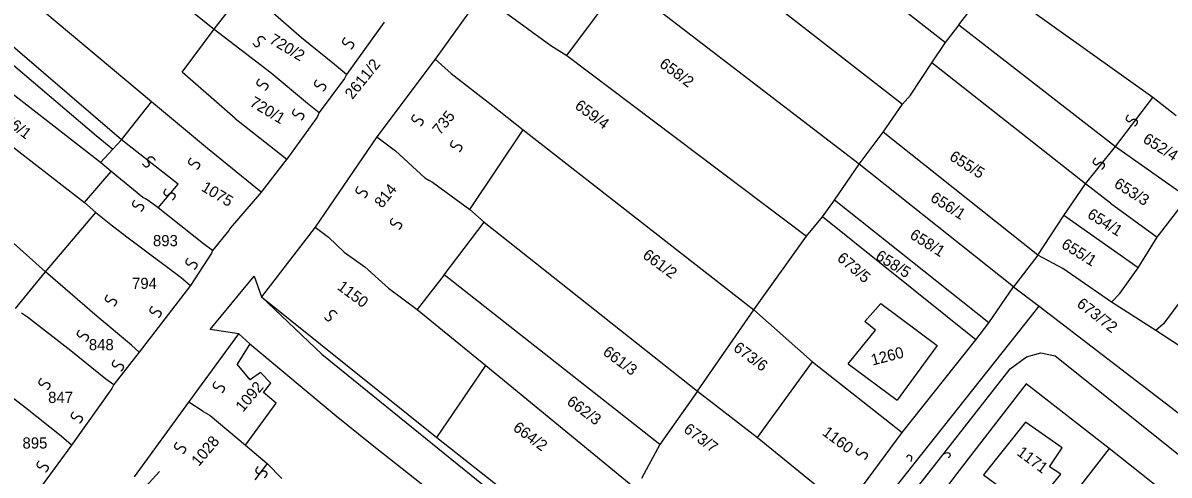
# Model space of a CAD drawing. Extents: x -581999 to -572728, y -1219553 to -1212032.
# Drawn here: x -577734.8 to -577529.2, y -1214895.3 to -1214814.1 of the extents above; entities that cross this region are included whole.
import ezdxf

# ---------------------------------------------------------------- set-up
doc = ezdxf.new("R2010")
doc.units = 0
for name, color, linetype in [('Vrstva 1', 7, 'Continuous'), ('Vrstva 2', 7, 'Continuous'), ('Vrstva 4', 7, 'Continuous'), ('Vrstva 6', 7, 'Continuous')]:
    doc.layers.add(name, color=color, linetype=linetype)

msp = doc.modelspace()

# ---------------------------------------------------------------- linework, layer by layer
at = {"layer": 'Vrstva 1'}
for p, q in [((-577548.056, -1214848.672), (-577544.197, -1214842.995)), ((-577552.774, -1214855.823), (-577548.056, -1214848.672)), ((-577534.754, -1214858.098), (-577548.056, -1214848.672)), ((-577700.798, -1214855), (-577700.97, -1214855.459)), ((-577700.97, -1214855.459), (-577704.745, -1214861.238)), ((-577701.189, -1214869.169), (-577693.334, -1214859.561)), ((-577693.334, -1214859.561), (-577691.998, -1214863.305)), ((-577704.745, -1214861.238), (-577713.952, -1214873.202)), ((-577681.203, -1214873.576), (-577691.998, -1214863.305)), ((-577602.086, -1214927.442), (-577552.514, -1214864.961)), ((-577696.075, -1214869.89), (-577701.189, -1214869.169)), ((-577554.783, -1214874.062), (-577552.226, -1214873.353)), ((-577552.226, -1214873.353), (-577549.644, -1214873.861)), ((-577681.203, -1214873.576), (-577612.266, -1214929.311)), ((-577557.705, -1214876.188), (-577554.783, -1214874.062)), ((-577549.644, -1214873.861), (-577480.978, -1214928.785)), ((-577599.697, -1214929.758), (-577557.705, -1214876.188)), ((-577702.462, -1214883.865), (-577705.058, -1214882.189))]:
    msp.add_line(p, q, dxfattribs=at)
for points in [[(-577747.607, -1214777.644), (-577700.52, -1214815.294)], [(-577717.101, -1214835.147), (-577773.13, -1214787)], [(-577711.749, -1214828.273), (-577757.801, -1214789.75)], [(-577602.684, -1214791.504), (-577569.32, -1214817.641)], [(-577770.074, -1214801.603), (-577765.899, -1214796.69), (-577721.694, -1214834.344), (-577718.663, -1214836.797)], [(-577610.911, -1214802.293), (-577577.009, -1214828.694)], [(-577637.213, -1214820.018), (-577627.323, -1214806.643)], [(-577566.929, -1214814.48), (-577561.078, -1214806.816)], [(-577527.934, -1214830.82), (-577532.103, -1214827.51), (-577561.078, -1214806.816)], [(-577700.52, -1214815.294), (-577695.029, -1214808.235)], [(-577652.443, -1214808.875), (-577660.874, -1214820.637)], [(-577584.785, -1214839.458), (-577624.766, -1214808.82)], [(-577684.856, -1214816.822), (-577690.887, -1214811.561)], [(-577649.144, -1214811.619), (-577640.086, -1214818.2)], [(-577696.723, -1214831.286), (-577706.264, -1214822.979), (-577700.52, -1214815.294)], [(-577700.52, -1214815.294), (-577690.3, -1214823.096)], [(-577669.983, -1214814.006), (-577676.755, -1214823.38)], [(-577569.32, -1214817.641), (-577567.041, -1214814.704), (-577566.929, -1214814.48)], [(-577566.929, -1214814.48), (-577538.793, -1214836.285), (-577525.86, -1214845.454)], [(-577678.915, -1214821.626), (-577684.856, -1214816.822)], [(-577571.772, -1214821.326), (-577569.32, -1214817.641)], [(-577640.086, -1214818.2), (-577637.213, -1214820.018)], [(-577637.213, -1214820.018), (-577594.254, -1214852.405)], [(-577720.879, -1214839.207), (-577744.685, -1214820.71)], [(-577676.755, -1214823.38), (-577678.915, -1214821.626)], [(-577660.874, -1214820.637), (-577671.346, -1214834.593)], [(-577660.874, -1214820.637), (-577657.985, -1214823.242)], [(-577575.563, -1214827.133), (-577571.772, -1214821.326)], [(-577539.717, -1214846.496), (-577544.197, -1214842.995), (-577571.772, -1214821.326)], [(-577690.3, -1214823.096), (-577683.729, -1214828.543)], [(-577676.755, -1214823.38), (-577677.13, -1214824.143), (-577681.659, -1214830.206)], [(-577657.985, -1214823.242), (-577650.807, -1214828.796)], [(-577749.226, -1214826.599), (-577723.731, -1214846.371)], [(-577717.101, -1214835.147), (-577711.749, -1214828.273)], [(-577701.666, -1214836.676), (-577711.749, -1214828.273)], [(-577577.009, -1214828.694), (-577575.563, -1214827.133)], [(-577730.767, -1214858.778), (-577764.668, -1214828.469), (-577768.339, -1214829.671)], [(-577681.659, -1214830.206), (-577682.033, -1214831.059), (-577687.459, -1214838.567)], [(-577683.729, -1214828.543), (-577681.659, -1214830.206)], [(-577650.807, -1214828.796), (-577645.065, -1214833.33)], [(-577580.464, -1214833.719), (-577577.009, -1214828.694)], [(-577696.723, -1214831.286), (-577689.708, -1214836.775)], [(-577654.62, -1214847.611), (-577645.065, -1214833.33)], [(-577645.065, -1214833.33), (-577603.67, -1214865.62)], [(-577584.785, -1214839.458), (-577580.464, -1214833.719)], [(-577552.774, -1214855.823), (-577580.464, -1214833.719)], [(-577718.663, -1214836.797), (-577717.101, -1214835.147)], [(-577671.346, -1214834.593), (-577682.381, -1214850.79)], [(-577671.346, -1214834.593), (-577667.983, -1214837.072)], [(-577720.879, -1214839.207), (-577718.663, -1214836.797)], [(-577692.088, -1214844.479), (-577701.666, -1214836.676)], [(-577687.459, -1214838.567), (-577687.844, -1214838.976), (-577692.088, -1214844.479)], [(-577689.708, -1214836.775), (-577687.459, -1214838.567)], [(-577667.983, -1214837.072), (-577662.684, -1214841.939), (-577662.021, -1214842.337)], [(-577530.475, -1214851.501), (-577525.86, -1214845.454), (-577519.424, -1214837.028)], [(-577718.988, -1214840.776), (-577720.879, -1214839.207)], [(-577589.243, -1214845.934), (-577584.785, -1214839.458)], [(-577557.084, -1214861.5), (-577584.785, -1214839.458)], [(-577723.731, -1214846.371), (-577718.988, -1214840.776)], [(-577713.282, -1214845.445), (-577718.988, -1214840.776)], [(-577662.021, -1214842.337), (-577661.358, -1214842.735), (-577654.62, -1214847.611)], [(-577692.088, -1214844.479), (-577692.361, -1214844.843), (-577697.621, -1214850.934)], [(-577723.731, -1214846.371), (-577721.75, -1214848.124)], [(-577712.365, -1214846.024), (-577712.907, -1214845.638), (-577713.282, -1214845.445)], [(-577710.522, -1214847.336), (-577712.365, -1214846.024)], [(-577591.38, -1214848.924), (-577589.243, -1214845.934)], [(-577561.54, -1214867.975), (-577589.243, -1214845.934)], [(-577539.717, -1214846.496), (-577531.358, -1214852.586)], [(-577730.767, -1214858.778), (-577721.75, -1214848.124)], [(-577721.75, -1214848.124), (-577718.76, -1214850.552)], [(-577702.419, -1214853.799), (-577710.522, -1214847.336)], [(-577654.62, -1214847.611), (-577652.082, -1214849.875)], [(-577718.76, -1214850.552), (-577715.945, -1214852.669)], [(-577697.621, -1214850.934), (-577697.884, -1214851.366), (-577700.798, -1214855)], [(-577682.381, -1214850.79), (-577691.998, -1214863.305), (-577660.574, -1214888.531)], [(-577682.381, -1214850.79), (-577679.964, -1214852.554)], [(-577659.241, -1214859.335), (-577652.082, -1214849.875)], [(-577652.082, -1214849.875), (-577613.823, -1214880.19)], [(-577594.254, -1214852.405), (-577591.38, -1214848.924)], [(-577563.878, -1214870.987), (-577591.38, -1214848.924)], [(-577715.945, -1214852.669), (-577706.416, -1214859.808)], [(-577679.964, -1214852.554), (-577677.205, -1214855.268)], [(-577603.67, -1214865.62), (-577594.254, -1214852.405)], [(-577538.052, -1214862.662), (-577534.754, -1214858.098), (-577531.358, -1214852.586), (-577530.475, -1214851.501)], [(-577700.798, -1214855), (-577702.419, -1214853.799)], [(-577677.205, -1214855.268), (-577673.448, -1214857.878)], [(-577552.774, -1214855.823), (-577557.084, -1214861.5)], [(-577548.247, -1214858.213), (-577552.774, -1214855.823)], [(-577736.161, -1214865.367), (-577730.767, -1214858.778)], [(-577721.494, -1214866.804), (-577730.767, -1214858.778)], [(-577673.448, -1214857.878), (-577669.253, -1214861.724)], [(-577539.534, -1214864.221), (-577548.247, -1214858.213)], [(-577522.093, -1214857.171), (-577530.222, -1214868.102)], [(-577706.416, -1214859.808), (-577704.745, -1214861.238)], [(-577659.241, -1214859.335), (-577664.062, -1214865.579)], [(-577620.542, -1214889.762), (-577659.241, -1214859.335)], [(-577669.253, -1214861.724), (-577664.062, -1214865.579)], [(-577561.54, -1214867.975), (-577557.084, -1214861.5)], [(-577557.084, -1214861.5), (-577552.514, -1214864.961), (-577474.403, -1214924.888)], [(-577539.534, -1214864.221), (-577538.052, -1214862.662)], [(-577586.797, -1214875.311), (-577581.884, -1214869.252), (-577583.756, -1214867.716), (-577580.923, -1214864.498), (-577570.808, -1214871.999), (-577577.994, -1214881.849)], [(-577531.591, -1214869.326), (-577539.534, -1214864.221)], [(-577735.06, -1214866.132), (-577733.959, -1214866.896), (-577726.213, -1214872.899)], [(-577715.338, -1214871.968), (-577721.494, -1214866.804)], [(-577664.062, -1214865.579), (-577651.765, -1214875.618)], [(-577613.823, -1214880.19), (-577603.67, -1214865.62)], [(-577603.67, -1214865.62), (-577593.157, -1214874.941)], [(-577563.878, -1214870.987), (-577561.54, -1214867.975)], [(-577530.222, -1214868.102), (-577531.591, -1214869.326)], [(-577523.65, -1214874.542), (-577531.591, -1214869.326)], [(-577714.791, -1214895.569), (-577705.058, -1214882.189), (-577696.075, -1214869.89), (-577694.087, -1214871.7)], [(-577577.097, -1214887.628), (-577563.878, -1214870.987)], [(-577726.213, -1214872.899), (-577719.91, -1214877.975)], [(-577713.952, -1214873.202), (-577718.469, -1214878.991)], [(-577713.952, -1214873.202), (-577715.338, -1214871.968)], [(-577694.087, -1214871.7), (-577696.356, -1214875.348)], [(-577694.087, -1214871.7), (-577678.626, -1214884.607)], [(-577694.881, -1214889.88), (-577689.381, -1214882.379), (-577691.631, -1214880.457), (-577690.308, -1214878.752), (-577692.182, -1214876.833), (-577694.068, -1214878.154), (-577696.356, -1214875.348)], [(-577603.044, -1214888.541), (-577593.157, -1214874.941)], [(-577593.157, -1214874.941), (-577577.097, -1214887.628)], [(-577586.797, -1214875.311), (-577577.994, -1214881.849)], [(-577660.574, -1214888.531), (-577651.765, -1214875.618)], [(-577651.765, -1214875.618), (-577625.058, -1214897.575)], [(-577718.469, -1214878.991), (-577718.834, -1214879.716), (-577726.097, -1214889.907)], [(-577719.91, -1214877.975), (-577718.469, -1214878.991)], [(-577554.825, -1214878.905), (-577567.255, -1214894.961), (-577573.728, -1214903.608), (-577575.654, -1214907.252)], [(-577539.921, -1214890.466), (-577554.825, -1214878.905)], [(-577734.33, -1214883.219), (-577736.764, -1214881.349)], [(-577613.823, -1214880.19), (-577620.542, -1214889.762)], [(-577613.823, -1214880.19), (-577603.044, -1214888.541)], [(-577727.937, -1214888.295), (-577734.33, -1214883.219)], [(-577702.462, -1214883.865), (-577701.244, -1214884.58), (-577694.881, -1214889.88)], [(-577678.626, -1214884.607), (-577672.441, -1214889.588)], [(-577554.953, -1214885.746), (-577562.512, -1214895.211), (-577553.899, -1214901.554), (-577548.608, -1214895.12), (-577550.668, -1214893.772), (-577548.398, -1214890.362), (-577554.953, -1214885.746)], [(-577587.23, -1214901.351), (-577577.097, -1214887.628)], [(-577726.097, -1214889.907), (-577737.394, -1214905.307)], [(-577726.097, -1214889.907), (-577727.937, -1214888.295)], [(-577694.881, -1214889.88), (-577691.016, -1214893.162)], [(-577672.441, -1214889.588), (-577638.078, -1214916.756), (-577639.86, -1214918.987)], [(-577660.574, -1214888.531), (-577633.597, -1214909.776)], [(-577620.542, -1214889.762), (-577623.865, -1214895.874)], [(-577603.044, -1214888.541), (-577587.23, -1214901.351)], [(-577539.921, -1214890.466), (-577553.545, -1214908.032)], [(-577524.564, -1214902.68), (-577539.921, -1214890.466)], [(-577691.016, -1214893.162), (-577688.368, -1214895.874)]]:
    msp.add_lwpolyline(points, dxfattribs=at)
at = {"layer": 'Vrstva 4'}
for p, q in [((-577538.793, -1214836.285), (-577532.103, -1214827.51)), ((-577544.197, -1214842.995), (-577538.793, -1214836.285))]:
    msp.add_line(p, q, dxfattribs=at)
for points in [[(-577706.984, -1214843.089), (-577717.101, -1214835.147)], [(-577710.522, -1214847.336), (-577706.984, -1214843.089)], [(-577691.016, -1214893.162), (-577693.207, -1214896.103)], [(-577710.313, -1214894.612), (-577712.842, -1214897.34)]]:
    msp.add_lwpolyline(points, dxfattribs=at)
at = {"layer": 'Vrstva 6'}
for points, degree in [([(-577693.561, -1214817.824), (-577693.081, -1214818.531), (-577692.387, -1214818.22), (-577692.31, -1214817.82), (-577692.546, -1214817.475), (-577692.631, -1214817.143), (-577692.549, -1214816.853), (-577692.405, -1214816.673), (-577692.169, -1214816.545), (-577691.804, -1214816.581), (-577691.377, -1214817.02), (-577691.322, -1214817.193)], 2), ([(-577677.061, -1214816.788), (-577677.648, -1214817.41), (-577677.193, -1214818.019), (-577676.787, -1214818.007), (-577676.501, -1214817.702), (-577676.195, -1214817.548), (-577675.895, -1214817.564), (-577675.688, -1214817.666), (-577675.512, -1214817.869), (-577675.467, -1214818.233), (-577675.802, -1214818.745), (-577675.96, -1214818.837)], 2), ([(-577692.45, -1214824.191), (-577693.037, -1214824.813), (-577692.582, -1214825.422), (-577692.176, -1214825.41), (-577691.89, -1214825.105), (-577691.584, -1214824.951), (-577691.284, -1214824.967), (-577691.077, -1214825.069), (-577690.901, -1214825.272), (-577690.856, -1214825.636), (-577691.191, -1214826.148), (-577691.349, -1214826.24)], 2), ([(-577682.086, -1214824.348), (-577682.673, -1214824.97), (-577682.218, -1214825.579), (-577681.812, -1214825.567), (-577681.526, -1214825.262), (-577681.22, -1214825.108), (-577680.92, -1214825.124), (-577680.713, -1214825.226), (-577680.537, -1214825.429), (-577680.492, -1214825.793), (-577680.827, -1214826.305), (-577680.985, -1214826.397)], 2), ([(-577686.012, -1214829.546), (-577686.599, -1214830.168), (-577686.144, -1214830.777), (-577685.738, -1214830.765), (-577685.452, -1214830.46), (-577685.146, -1214830.306), (-577684.846, -1214830.322), (-577684.639, -1214830.424), (-577684.463, -1214830.627), (-577684.418, -1214830.991), (-577684.753, -1214831.503), (-577684.911, -1214831.595)], 2), ([(-577664.615, -1214830.596), (-577665.202, -1214831.218), (-577664.747, -1214831.827), (-577664.341, -1214831.815), (-577664.055, -1214831.51), (-577663.749, -1214831.356), (-577663.449, -1214831.372), (-577663.242, -1214831.474), (-577663.066, -1214831.677), (-577663.021, -1214832.041), (-577663.356, -1214832.553), (-577663.514, -1214832.645)], 2), ([(-577536.477, -1214830.622), (-577537.064, -1214831.244), (-577536.609, -1214831.853), (-577536.203, -1214831.841), (-577535.917, -1214831.536), (-577535.611, -1214831.382), (-577535.311, -1214831.398), (-577535.104, -1214831.5), (-577534.928, -1214831.703), (-577534.883, -1214832.067), (-577535.218, -1214832.579), (-577535.376, -1214832.671)], 2), ([(-577657.668, -1214835.238), (-577658.255, -1214835.86), (-577657.8, -1214836.469), (-577657.394, -1214836.457), (-577657.108, -1214836.152), (-577656.802, -1214835.998), (-577656.502, -1214836.014), (-577656.295, -1214836.116), (-577656.119, -1214836.319), (-577656.074, -1214836.683), (-577656.409, -1214837.195), (-577656.567, -1214837.287)], 2), ([(-577713.347, -1214839.402), (-577712.867, -1214840.109), (-577712.173, -1214839.798), (-577712.096, -1214839.398), (-577712.332, -1214839.053), (-577712.417, -1214838.721), (-577712.335, -1214838.431), (-577712.191, -1214838.251), (-577711.955, -1214838.123), (-577711.59, -1214838.159), (-577711.163, -1214838.598), (-577711.108, -1214838.771)], 2), ([(-577704.699, -1214838.366), (-577705.286, -1214838.988), (-577704.831, -1214839.597), (-577704.425, -1214839.585), (-577704.139, -1214839.28), (-577703.833, -1214839.126), (-577703.533, -1214839.142), (-577703.326, -1214839.244), (-577703.15, -1214839.447), (-577703.105, -1214839.811), (-577703.44, -1214840.323), (-577703.598, -1214840.415)], 2), ([(-577542.395, -1214838.365), (-577542.982, -1214838.987), (-577542.527, -1214839.596), (-577542.121, -1214839.584), (-577541.835, -1214839.279), (-577541.529, -1214839.125), (-577541.229, -1214839.141), (-577541.022, -1214839.243), (-577540.846, -1214839.446), (-577540.801, -1214839.81), (-577541.136, -1214840.322), (-577541.294, -1214840.414)], 2), ([(-577709.096, -1214843.878), (-577709.683, -1214844.5), (-577709.228, -1214845.109), (-577708.822, -1214845.097), (-577708.536, -1214844.792), (-577708.23, -1214844.638), (-577707.93, -1214844.654), (-577707.723, -1214844.756), (-577707.547, -1214844.959), (-577707.502, -1214845.323), (-577707.837, -1214845.835), (-577707.995, -1214845.927)], 2), ([(-577674.65, -1214843.493), (-577675.237, -1214844.115), (-577674.782, -1214844.724), (-577674.376, -1214844.712), (-577674.09, -1214844.407), (-577673.784, -1214844.253), (-577673.484, -1214844.269), (-577673.277, -1214844.371), (-577673.101, -1214844.574), (-577673.056, -1214844.938), (-577673.391, -1214845.45), (-577673.549, -1214845.542)], 2), ([(-577714.75, -1214845.926), (-577715.337, -1214846.548), (-577714.882, -1214847.157), (-577714.476, -1214847.145), (-577714.19, -1214846.84), (-577713.884, -1214846.686), (-577713.584, -1214846.702), (-577713.377, -1214846.804), (-577713.201, -1214847.007), (-577713.156, -1214847.371), (-577713.491, -1214847.883), (-577713.649, -1214847.975)], 2), ([(-577668.475, -1214849.167), (-577669.062, -1214849.789), (-577668.607, -1214850.398), (-577668.201, -1214850.386), (-577667.915, -1214850.081), (-577667.609, -1214849.927), (-577667.309, -1214849.943), (-577667.102, -1214850.045), (-577666.926, -1214850.248), (-577666.881, -1214850.612), (-577667.216, -1214851.124), (-577667.374, -1214851.216)], 2), ([(-577705.171, -1214856.321), (-577705.758, -1214856.943), (-577705.303, -1214857.552), (-577704.897, -1214857.54), (-577704.611, -1214857.235), (-577704.305, -1214857.081), (-577704.005, -1214857.097), (-577703.798, -1214857.199), (-577703.622, -1214857.402), (-577703.577, -1214857.766), (-577703.912, -1214858.278), (-577704.07, -1214858.37)], 2), ([(-577719.618, -1214862.937), (-577720.205, -1214863.559), (-577719.75, -1214864.168), (-577719.344, -1214864.156), (-577719.058, -1214863.851), (-577718.752, -1214863.697), (-577718.452, -1214863.713), (-577718.245, -1214863.815), (-577718.069, -1214864.018), (-577718.024, -1214864.382), (-577718.359, -1214864.894), (-577718.517, -1214864.986)], 2), ([(-577711.609, -1214864.984), (-577712.196, -1214865.606), (-577711.741, -1214866.215), (-577711.335, -1214866.203), (-577711.049, -1214865.898), (-577710.743, -1214865.744), (-577710.443, -1214865.76), (-577710.236, -1214865.862), (-577710.06, -1214866.065), (-577710.015, -1214866.429), (-577710.35, -1214866.941), (-577710.508, -1214867.033)], 2), ([(-577680.719, -1214866.984), (-577680.239, -1214867.691), (-577679.545, -1214867.38), (-577679.468, -1214866.98), (-577679.704, -1214866.635), (-577679.789, -1214866.303), (-577679.707, -1214866.013), (-577679.563, -1214865.833), (-577679.327, -1214865.705), (-577678.962, -1214865.741), (-577678.535, -1214866.18), (-577678.48, -1214866.353)], 2), ([(-577724.643, -1214869.237), (-577725.23, -1214869.859), (-577724.775, -1214870.468), (-577724.369, -1214870.456), (-577724.083, -1214870.151), (-577723.777, -1214869.997), (-577723.477, -1214870.013), (-577723.27, -1214870.115), (-577723.094, -1214870.318), (-577723.049, -1214870.682), (-577723.384, -1214871.194), (-577723.542, -1214871.286)], 2), ([(-577718.361, -1214874.592), (-577718.948, -1214875.214), (-577718.493, -1214875.823), (-577718.087, -1214875.811), (-577717.801, -1214875.506), (-577717.495, -1214875.352), (-577717.195, -1214875.368), (-577716.988, -1214875.47), (-577716.812, -1214875.673), (-577716.767, -1214876.037), (-577717.102, -1214876.549), (-577717.26, -1214876.641)], 2), ([(-577731.552, -1214877.9), (-577732.139, -1214878.522), (-577731.684, -1214879.131), (-577731.278, -1214879.119), (-577730.992, -1214878.814), (-577730.686, -1214878.66), (-577730.386, -1214878.676), (-577730.179, -1214878.778), (-577730.003, -1214878.981), (-577729.958, -1214879.345), (-577730.293, -1214879.857), (-577730.451, -1214879.949)], 2), ([(-577700.247, -1214878.465), (-577700.834, -1214879.087), (-577700.379, -1214879.696), (-577699.973, -1214879.684), (-577699.687, -1214879.379), (-577699.381, -1214879.225), (-577699.081, -1214879.241), (-577698.874, -1214879.343), (-577698.698, -1214879.546), (-577698.653, -1214879.91), (-577698.988, -1214880.422), (-577699.146, -1214880.514)], 2), ([(-577725.742, -1214883.885), (-577726.329, -1214884.507), (-577725.874, -1214885.116), (-577725.468, -1214885.104), (-577725.182, -1214884.799), (-577724.876, -1214884.645), (-577724.576, -1214884.661), (-577724.369, -1214884.763), (-577724.193, -1214884.966), (-577724.148, -1214885.33), (-577724.483, -1214885.842), (-577724.641, -1214885.934)], 2), ([(-577707.209, -1214889.37), (-577707.796, -1214889.992), (-577707.341, -1214890.601), (-577706.935, -1214890.589), (-577706.649, -1214890.284), (-577706.343, -1214890.13), (-577706.043, -1214890.146), (-577705.836, -1214890.248), (-577705.66, -1214890.451), (-577705.615, -1214890.815), (-577705.95, -1214891.327), (-577706.108, -1214891.419)], 2), ([(-577584.926, -1214890.403), (-577585.513, -1214891.025), (-577585.058, -1214891.634), (-577584.652, -1214891.622), (-577584.366, -1214891.317), (-577584.06, -1214891.163), (-577583.76, -1214891.179), (-577583.553, -1214891.281), (-577583.377, -1214891.484), (-577583.332, -1214891.848), (-577583.667, -1214892.36), (-577583.825, -1214892.452)], 2), ([(-577575.495, -1214892.809), (-577575.144, -1214892.03), (-577575.772, -1214891.602), (-577576.148, -1214891.743), (-577576.262, -1214891.991), (-577576.327, -1214892.092)], 3), ([(-577569.642, -1214891.449), (-577568.912, -1214891.003), (-577568.409, -1214891.573), (-577568.503, -1214891.963), (-577568.735, -1214892.107), (-577568.827, -1214892.184)], 3), ([(-577731.866, -1214892.705), (-577732.453, -1214893.327), (-577731.998, -1214893.936), (-577731.592, -1214893.924), (-577731.306, -1214893.619), (-577731, -1214893.465), (-577730.7, -1214893.481), (-577730.493, -1214893.583), (-577730.317, -1214893.786), (-577730.272, -1214894.15), (-577730.607, -1214894.662), (-577730.765, -1214894.754)], 2), ([(-577692.633, -1214893.732), (-577693.22, -1214894.354), (-577692.765, -1214894.963), (-577692.359, -1214894.951), (-577692.073, -1214894.646), (-577691.767, -1214894.492), (-577691.467, -1214894.508), (-577691.26, -1214894.61), (-577691.084, -1214894.813), (-577691.039, -1214895.177), (-577691.374, -1214895.689), (-577691.532, -1214895.781)], 2)]:
    msp.add_open_spline(points, degree=degree, dxfattribs=at)

# ---------------------------------------------------------------- texts
at = {"layer": 'Vrstva 2'}
for s, rotation, p in [('720/2', 329.01417, (-577690.765, -1214817.657)), ('2611/2', 51.17731, (-577675.697, -1214827.984)), ('658/2', 323.42903, (-577620.781, -1214821.857)), ('720/1', 329.01417, (-577694.278, -1214828.913)), ('659/4', 323.42903, (-577635.958, -1214829.349)), ('706/1', 322.91464, (-577739.589, -1214831.075)), ('735', 51.17731, (-577659.968, -1214834.38)), ('652/4', 327.82777, (-577534.061, -1214835.455)), ('655/5', 327.82777, (-577568.771, -1214838.598)), ('653/3', 327.82777, (-577539.235, -1214843.476)), ('1075', 329.01417, (-577702.971, -1214844.144)), ('814', 51.17731, (-577670.392, -1214847.498)), ('656/1', 327.82777, (-577572.189, -1214845.984)), ('654/1', 327.82777, (-577544.033, -1214848.957)), ('658/1', 327.82777, (-577575.877, -1214852.646)), ('655/1', 327.82777, (-577548.681, -1214854.347)), ('661/2', 323.42903, (-577623.795, -1214856.16)), ('658/5', 327.82777, (-577582.016, -1214856.434)), ('673/5', 319.44602, (-577588.905, -1214856.594)), ('1150', 323.42903, (-577678.581, -1214861.815)), ('673/72', 322.28093, (-577545.912, -1214864.868)), ('673/6', 323.42903, (-577607.524, -1214872.789)), ('661/3', 323.42903, (-577630.922, -1214873.533)), ('1260', 14.58334, (-577582.385, -1214875.618)), ('1092', 49.92375, (-577695.339, -1214884.082)), ('662/3', 323.42903, (-577637.393, -1214882.43)), ('664/2', 323.42903, (-577647.047, -1214887.103)), ('673/7', 323.42903, (-577616.445, -1214887.387)), ('1160', 323.42903, (-577591.571, -1214887.93)), ('1028', 49.92375, (-577703.26, -1214893.814)), ('1171', 323.42903, (-577556.661, -1214891.545))]:
    msp.add_text(s, height=2, rotation=rotation, dxfattribs=at).set_placement(p)
for s, p in [('893', (-577711.476, -1214854.198)), ('794', (-577715.233, -1214861.866)), ('848', (-577722.978, -1214872.858)), ('847', (-577730.285, -1214882.317)), ('895', (-577734.882, -1214890.497))]:
    msp.add_text(s, height=2, dxfattribs=at).set_placement(p)

doc.saveas('drawing.dxf')
